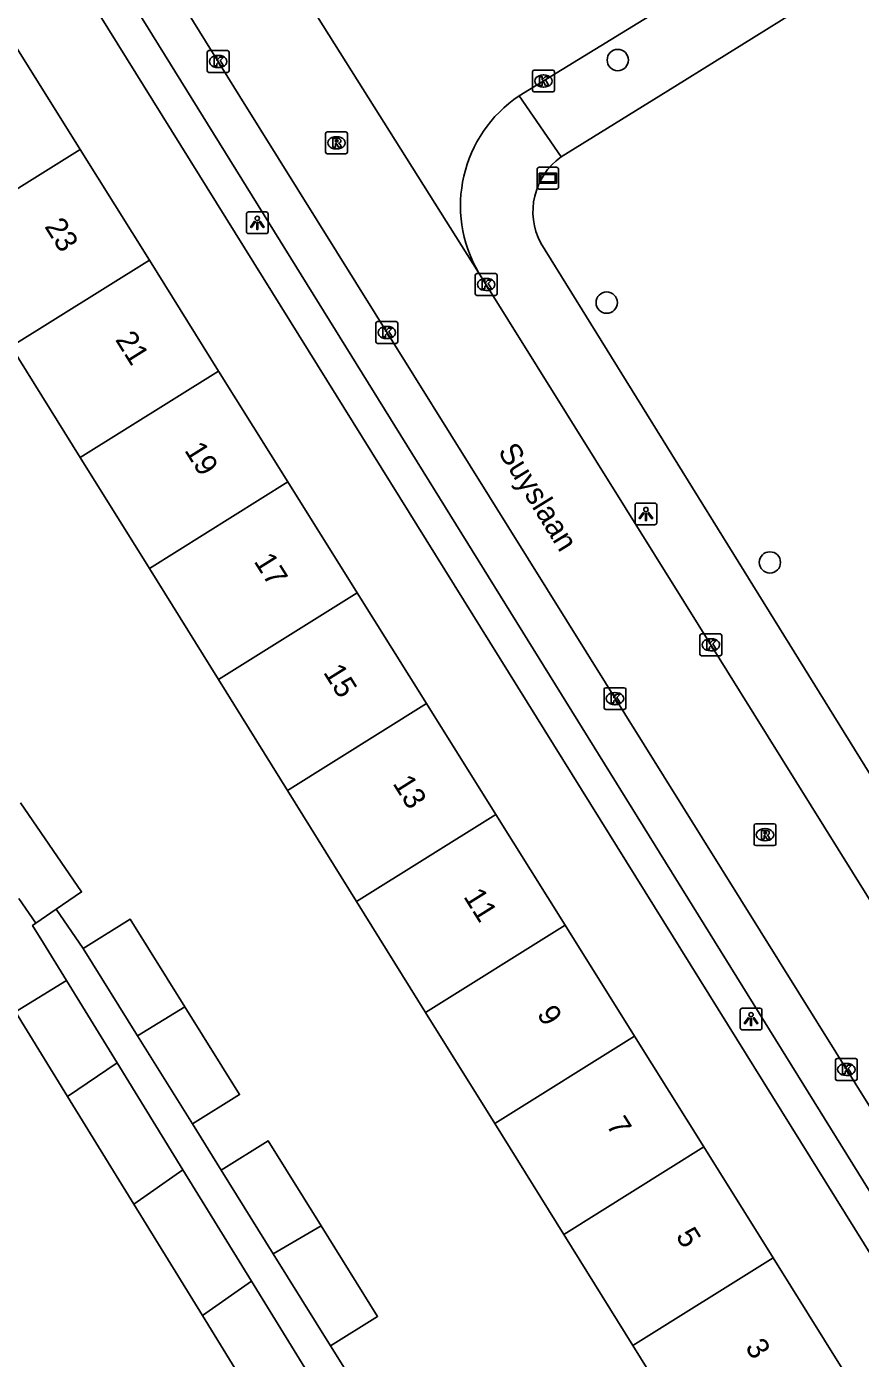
# Model space of a CAD drawing. Extents: x 160037 to 160839, y 385326 to 386441.
# Drawn here: x 160189.1 to 160227.4, y 386041.7 to 386102.8 of the extents above; entities that cross this region are included whole.
import ezdxf

# ---------------------------------------------------------------- set-up
doc = ezdxf.new("R2010")
doc.units = 0
for name, color, linetype in [('IMGEO_Boom', 7, 'Continuous'), ('IMGEO_Kolk', 7, 'Continuous'), ('IMGEO_Lichtpunt', 7, 'Continuous'), ('IMGEO_Openbare_ruimte_label', 7, 'Continuous'), ('IMGEO_Pand', 7, 'Continuous'), ('IMGEO_Pand_nummerreeks', 7, 'Continuous'), ('IMGEO_Rijbaan_lokaal_open', 7, 'Continuous'), ('IMGEO_Rioolput', 7, 'Continuous'), ('IMGEO_Straatnaambord', 7, 'Continuous'), ('IMGEO_Voetpad_open', 7, 'Continuous')]:
    doc.layers.add(name, color=color, linetype=linetype)

msp = doc.modelspace()

# ---------------------------------------------------------------- linework, layer by layer
at = {"layer": 'IMGEO_Boom'}
for centre in [(160216.279, 386101.253), (160215.77, 386090.121), (160223.261, 386078.194)]:
    msp.add_circle(centre, 0.489, dxfattribs=at)
at = {"layer": 'IMGEO_Kolk'}
for p, q in [((160197.508, 386101.686), (160198.36, 386101.686)), ((160197.433, 386100.76), (160197.433, 386101.612)), ((160197.921, 386101.466), (160197.946, 386101.466)), ((160198.434, 386101.612), (160198.434, 386100.76)), ((160198.36, 386100.686), (160197.508, 386100.686)), ((160197.944, 386100.906), (160197.919, 386100.906)), ((160212.367, 386099.863), (160212.367, 386100.715)), ((160212.442, 386100.789), (160213.294, 386100.789)), ((160212.855, 386100.569), (160212.88, 386100.569)), ((160213.368, 386100.715), (160213.368, 386099.863)), ((160213.294, 386099.789), (160212.442, 386099.789)), ((160212.878, 386100.009), (160212.853, 386100.009)), ((160209.735, 386090.527), (160209.735, 386091.379)), ((160209.81, 386091.453), (160210.662, 386091.453)), ((160210.223, 386091.233), (160210.248, 386091.233)), ((160210.736, 386091.379), (160210.736, 386090.527)), ((160210.246, 386090.673), (160210.221, 386090.673)), ((160210.662, 386090.453), (160209.81, 386090.453)), ((160205.176, 386088.321), (160205.176, 386089.173)), ((160205.251, 386089.247), (160206.103, 386089.247)), ((160205.664, 386089.027), (160205.689, 386089.027)), ((160206.177, 386089.173), (160206.177, 386088.321)), ((160206.103, 386088.247), (160205.251, 386088.247)), ((160205.687, 386088.467), (160205.662, 386088.467)), ((160220.051, 386073.989), (160220.051, 386074.841)), ((160220.126, 386074.915), (160220.978, 386074.915)), ((160221.052, 386074.841), (160221.052, 386073.989)), ((160220.562, 386074.135), (160220.537, 386074.135)), ((160220.539, 386074.695), (160220.564, 386074.695)), ((160220.978, 386073.915), (160220.126, 386073.915)), ((160215.647, 386071.521), (160215.647, 386072.373)), ((160215.722, 386072.447), (160216.574, 386072.447)), ((160216.648, 386072.373), (160216.648, 386071.521)), ((160216.158, 386071.667), (160216.133, 386071.667)), ((160216.135, 386072.227), (160216.16, 386072.227)), ((160216.574, 386071.447), (160215.722, 386071.447)), ((160226.27, 386054.5), (160226.27, 386055.352)), ((160226.345, 386055.426), (160227.197, 386055.426)), ((160226.758, 386055.206), (160226.783, 386055.206)), ((160227.271, 386055.352), (160227.271, 386054.5)), ((160226.781, 386054.646), (160226.756, 386054.646)), ((160227.197, 386054.426), (160226.345, 386054.426))]:
    msp.add_line(p, q, dxfattribs=at)
for points in [[(160197.508, 386101.686), (160198.36, 386101.686)], [(160197.433, 386100.76), (160197.433, 386101.612)], [(160197.754, 386101.386), (160197.877, 386101.386), (160197.877, 386101.235), (160198.007, 386101.386), (160198.171, 386101.386), (160198.025, 386101.235), (160198.178, 386100.986), (160198.026, 386100.986), (160197.941, 386101.15), (160197.877, 386101.083), (160197.877, 386100.986), (160197.754, 386100.986), (160197.754, 386101.386)], [(160198.434, 386101.612), (160198.434, 386100.76)], [(160198.36, 386100.686), (160197.508, 386100.686)], [(160212.367, 386099.863), (160212.367, 386100.715)], [(160212.442, 386100.789), (160213.294, 386100.789)], [(160212.688, 386100.489), (160212.811, 386100.489), (160212.811, 386100.338), (160212.941, 386100.489), (160213.105, 386100.489), (160212.959, 386100.338), (160213.112, 386100.089), (160212.96, 386100.089), (160212.875, 386100.253), (160212.811, 386100.186), (160212.811, 386100.089), (160212.688, 386100.089), (160212.688, 386100.489)], [(160213.368, 386100.715), (160213.368, 386099.863)], [(160213.294, 386099.789), (160212.442, 386099.789)], [(160209.735, 386090.527), (160209.735, 386091.379)], [(160209.81, 386091.453), (160210.662, 386091.453)], [(160210.736, 386091.379), (160210.736, 386090.527)], [(160210.056, 386091.153), (160210.179, 386091.153), (160210.179, 386091.002), (160210.309, 386091.153), (160210.473, 386091.153), (160210.327, 386091.002), (160210.48, 386090.753), (160210.328, 386090.753), (160210.243, 386090.917), (160210.179, 386090.85), (160210.179, 386090.753), (160210.056, 386090.753), (160210.056, 386091.153)], [(160210.662, 386090.453), (160209.81, 386090.453)], [(160205.176, 386088.321), (160205.176, 386089.173)], [(160205.251, 386089.247), (160206.103, 386089.247)], [(160205.497, 386088.947), (160205.62, 386088.947), (160205.62, 386088.796), (160205.75, 386088.947), (160205.914, 386088.947), (160205.768, 386088.796), (160205.921, 386088.547), (160205.769, 386088.547), (160205.684, 386088.711), (160205.62, 386088.644), (160205.62, 386088.547), (160205.497, 386088.547), (160205.497, 386088.947)], [(160206.177, 386089.173), (160206.177, 386088.321)], [(160206.103, 386088.247), (160205.251, 386088.247)], [(160220.051, 386073.989), (160220.051, 386074.841)], [(160220.126, 386074.915), (160220.978, 386074.915)], [(160221.052, 386074.841), (160221.052, 386073.989)], [(160220.372, 386074.615), (160220.495, 386074.615), (160220.495, 386074.464), (160220.625, 386074.615), (160220.789, 386074.615), (160220.643, 386074.464), (160220.796, 386074.215), (160220.644, 386074.215), (160220.559, 386074.379), (160220.495, 386074.312), (160220.495, 386074.215), (160220.372, 386074.215), (160220.372, 386074.615)], [(160220.978, 386073.915), (160220.126, 386073.915)], [(160215.647, 386071.521), (160215.647, 386072.373)], [(160215.722, 386072.447), (160216.574, 386072.447)], [(160216.648, 386072.373), (160216.648, 386071.521)], [(160215.968, 386072.147), (160216.091, 386072.147), (160216.091, 386071.996), (160216.221, 386072.147), (160216.385, 386072.147), (160216.239, 386071.996), (160216.392, 386071.747), (160216.24, 386071.747), (160216.155, 386071.911), (160216.091, 386071.844), (160216.091, 386071.747), (160215.968, 386071.747), (160215.968, 386072.147)], [(160216.574, 386071.447), (160215.722, 386071.447)], [(160226.27, 386054.5), (160226.27, 386055.352)], [(160226.345, 386055.426), (160227.197, 386055.426)], [(160227.271, 386055.352), (160227.271, 386054.5)], [(160226.591, 386055.126), (160226.714, 386055.126), (160226.714, 386054.975), (160226.844, 386055.126), (160227.008, 386055.126), (160226.862, 386054.975), (160227.015, 386054.726), (160226.863, 386054.726), (160226.778, 386054.89), (160226.714, 386054.823), (160226.714, 386054.726), (160226.591, 386054.726), (160226.591, 386055.126)], [(160227.197, 386054.426), (160226.345, 386054.426)]]:
    msp.add_lwpolyline(points, dxfattribs=at)
for centre, start, end in [((160197.51, 386101.61), 91.55205, 178.44795), ((160197.51, 386101.61), 91.55205, 178.44795), ((160198.358, 386101.61), 1.55205, 88.44795), ((160198.358, 386101.61), 1.55205, 88.44795), ((160197.51, 386100.762), 181.55205, 268.44795), ((160197.51, 386100.762), 181.55205, 268.44795), ((160198.358, 386100.762), 271.55205, 358.44795), ((160198.358, 386100.762), 271.55205, 358.44795), ((160212.444, 386100.713), 91.55205, 178.44795), ((160212.444, 386100.713), 91.55205, 178.44795), ((160213.292, 386100.713), 1.55205, 88.44795), ((160213.292, 386100.713), 1.55205, 88.44795), ((160212.444, 386099.865), 181.55205, 268.44795), ((160212.444, 386099.865), 181.55205, 268.44795), ((160213.292, 386099.865), 271.55205, 358.44795), ((160213.292, 386099.865), 271.55205, 358.44795), ((160209.812, 386091.377), 91.55205, 178.44795), ((160209.812, 386091.377), 91.55205, 178.44795), ((160210.66, 386091.377), 1.55205, 88.44795), ((160210.66, 386091.377), 1.55205, 88.44795), ((160209.812, 386090.529), 181.55205, 268.44795), ((160209.812, 386090.529), 181.55205, 268.44795), ((160210.66, 386090.529), 271.55205, 358.44795), ((160210.66, 386090.529), 271.55205, 358.44795), ((160205.253, 386089.171), 91.55205, 178.44795), ((160205.253, 386089.171), 91.55205, 178.44795), ((160206.101, 386089.171), 1.55205, 88.44795), ((160206.101, 386089.171), 1.55205, 88.44795), ((160205.253, 386088.323), 181.55205, 268.44795), ((160205.253, 386088.323), 181.55205, 268.44795), ((160206.101, 386088.323), 271.55205, 358.44795), ((160206.101, 386088.323), 271.55205, 358.44795), ((160220.128, 386074.839), 91.55205, 178.44795), ((160220.128, 386074.839), 91.55205, 178.44795), ((160220.976, 386074.839), 1.55205, 88.44795), ((160220.976, 386074.839), 1.55205, 88.44795), ((160220.128, 386073.991), 181.55205, 268.44795), ((160220.128, 386073.991), 181.55205, 268.44795), ((160220.976, 386073.991), 271.55205, 358.44795), ((160220.976, 386073.991), 271.55205, 358.44795), ((160215.724, 386072.371), 91.55205, 178.44795), ((160215.724, 386072.371), 91.55205, 178.44795), ((160216.572, 386072.371), 1.55205, 88.44795), ((160216.572, 386072.371), 1.55205, 88.44795), ((160215.724, 386071.523), 181.55205, 268.44795), ((160215.724, 386071.523), 181.55205, 268.44795), ((160216.572, 386071.523), 271.55205, 358.44795), ((160216.572, 386071.523), 271.55205, 358.44795), ((160226.347, 386055.35), 91.55205, 178.44795), ((160226.347, 386055.35), 91.55205, 178.44795), ((160227.195, 386055.35), 1.55205, 88.44795), ((160227.195, 386055.35), 1.55205, 88.44795), ((160226.347, 386054.502), 181.55205, 268.44795), ((160226.347, 386054.502), 181.55205, 268.44795), ((160227.195, 386054.502), 271.55205, 358.44795), ((160227.195, 386054.502), 271.55205, 358.44795)]:
    msp.add_arc(centre, 0.0765, start, end, dxfattribs=at)
for centre, major_axis, ratio, start_param, end_param in [((160197.92, 386101.186), (-0.387, 0.002), 0.722429, 4.712389, 7.853982), ((160197.945, 386101.186), (-0.39, 0.002), 0.717154, 1.570796, 4.712389), ((160212.854, 386100.289), (-0.387, 0.002), 0.722429, 4.712389, 7.853982), ((160212.879, 386100.289), (-0.39, 0.002), 0.717154, 1.570796, 4.712389), ((160210.222, 386090.953), (-0.387, 0.002), 0.722429, 4.712389, 7.853982), ((160210.247, 386090.953), (-0.39, 0.002), 0.717154, 1.570796, 4.712389), ((160205.663, 386088.747), (-0.387, 0.002), 0.722429, 4.712389, 7.853982), ((160205.688, 386088.747), (-0.39, 0.002), 0.717154, 1.570796, 4.712389), ((160220.538, 386074.415), (-0.387, 0.002), 0.722429, 4.712389, 7.853982), ((160220.563, 386074.415), (-0.39, 0.002), 0.717154, 1.570796, 4.712389), ((160216.134, 386071.947), (-0.387, 0.002), 0.722429, 4.712389, 7.853982), ((160216.159, 386071.947), (-0.39, 0.002), 0.717154, 1.570796, 4.712389), ((160226.757, 386054.926), (-0.387, 0.002), 0.722429, 4.712389, 7.853982), ((160226.782, 386054.926), (-0.39, 0.002), 0.717154, 1.570796, 4.712389)]:
    msp.add_ellipse(centre, major_axis=major_axis, ratio=ratio, start_param=start_param, end_param=end_param, dxfattribs=at)
at = {"layer": 'IMGEO_Lichtpunt'}
for p, q in [((160200.132, 386094.282), (160199.324, 386094.282)), ((160200.132, 386094.282), (160199.324, 386094.282)), ((160199.23, 386094.187), (160199.23, 386093.38)), ((160199.23, 386094.187), (160199.23, 386093.38)), ((160200.226, 386093.38), (160200.226, 386094.187)), ((160200.226, 386093.38), (160200.226, 386094.187)), ((160199.324, 386093.286), (160200.132, 386093.286)), ((160199.324, 386093.286), (160200.132, 386093.286)), ((160217.971, 386080.92), (160217.163, 386080.92)), ((160217.971, 386080.92), (160217.163, 386080.92)), ((160217.069, 386080.825), (160217.069, 386080.018)), ((160217.069, 386080.825), (160217.069, 386080.018)), ((160218.065, 386080.018), (160218.065, 386080.825)), ((160218.065, 386080.018), (160218.065, 386080.825)), ((160217.163, 386079.924), (160217.971, 386079.924)), ((160217.163, 386079.924), (160217.971, 386079.924)), ((160221.9, 386057.642), (160221.9, 386056.835)), ((160221.9, 386057.642), (160221.9, 386056.835)), ((160222.802, 386057.737), (160221.994, 386057.737)), ((160222.802, 386057.737), (160221.994, 386057.737)), ((160222.896, 386056.835), (160222.896, 386057.642)), ((160222.896, 386056.835), (160222.896, 386057.642)), ((160221.994, 386056.741), (160222.802, 386056.741)), ((160221.994, 386056.741), (160222.802, 386056.741))]:
    msp.add_line(p, q, dxfattribs=at)
for points in [[(160199.604, 386093.851), (160199.643, 386093.823), (160199.455, 386093.561), (160199.417, 386093.588), (160199.604, 386093.851)], [(160199.706, 386093.803), (160199.753, 386093.803), (160199.753, 386093.481), (160199.706, 386093.481), (160199.706, 386093.803)], [(160199.816, 386093.823), (160199.854, 386093.85), (160200.041, 386093.588), (160200.002, 386093.56), (160199.816, 386093.823)], [(160217.443, 386080.489), (160217.482, 386080.461), (160217.294, 386080.199), (160217.256, 386080.226), (160217.443, 386080.489)], [(160217.545, 386080.441), (160217.592, 386080.441), (160217.592, 386080.119), (160217.545, 386080.119), (160217.545, 386080.441)], [(160217.655, 386080.461), (160217.693, 386080.488), (160217.88, 386080.226), (160217.841, 386080.198), (160217.655, 386080.461)], [(160222.274, 386057.306), (160222.313, 386057.278), (160222.125, 386057.016), (160222.087, 386057.043), (160222.274, 386057.306)], [(160222.376, 386057.258), (160222.423, 386057.258), (160222.423, 386056.936), (160222.376, 386056.936), (160222.376, 386057.258)], [(160222.486, 386057.278), (160222.524, 386057.305), (160222.711, 386057.043), (160222.672, 386057.015), (160222.486, 386057.278)]]:
    msp.add_lwpolyline(points, dxfattribs=at)
for centre in [(160199.729, 386093.985), (160217.568, 386080.623), (160222.399, 386057.44)]:
    msp.add_circle(centre, 0.0994, dxfattribs=at)
for centre, start, end in [((160199.324, 386094.187), 90, 180), ((160199.324, 386094.187), 90, 180), ((160200.132, 386094.187), 0, 90), ((160200.132, 386094.187), 0, 90), ((160199.324, 386093.38), 180, 270), ((160199.324, 386093.38), 180, 270), ((160200.132, 386093.38), 270, 0), ((160200.132, 386093.38), 270, 360), ((160217.163, 386080.825), 90, 180), ((160217.163, 386080.825), 90, 180), ((160217.971, 386080.825), 0, 90), ((160217.971, 386080.825), 0, 90), ((160217.163, 386080.018), 180, 270), ((160217.163, 386080.018), 180, 270), ((160217.971, 386080.018), 270, 0), ((160217.971, 386080.018), 270, 360), ((160221.994, 386057.642), 90, 180), ((160221.994, 386057.642), 90, 180), ((160222.802, 386057.642), 0, 90), ((160222.802, 386057.642), 0, 90), ((160221.994, 386056.835), 180, 270), ((160221.994, 386056.835), 180, 270), ((160222.802, 386056.835), 270, 0), ((160222.802, 386056.835), 270, 360)]:
    msp.add_arc(centre, 0.0946, start, end, dxfattribs=at)
at = {"layer": 'IMGEO_Pand'}
for points in [[(160188.41, 386102.241), (160191.591, 386097.154)], [(160185.261, 386093.196), (160191.591, 386097.154)], [(160191.591, 386097.154), (160194.773, 386092.066)], [(160188.432, 386088.101), (160194.773, 386092.066)], [(160194.773, 386092.066), (160197.954, 386086.98)], [(160191.602, 386083.008), (160188.432, 386088.101)], [(160197.954, 386086.98), (160191.602, 386083.008)], [(160197.954, 386086.98), (160201.135, 386081.893)], [(160194.773, 386077.914), (160191.602, 386083.008)], [(160201.135, 386081.893), (160194.773, 386077.914)], [(160201.135, 386081.893), (160204.316, 386076.806)], [(160197.943, 386072.821), (160194.773, 386077.914)], [(160197.943, 386072.821), (160204.316, 386076.806)], [(160204.316, 386076.806), (160207.498, 386071.719)], [(160201.114, 386067.727), (160197.943, 386072.821)], [(160207.498, 386071.719), (160201.114, 386067.727)], [(160207.498, 386071.719), (160210.679, 386066.631)], [(160204.285, 386062.632), (160201.114, 386067.727)], [(160190.502, 386062.278), (160191.665, 386063.073), (160188.863, 386067.169)], [(160204.285, 386062.632), (160210.679, 386066.631)], [(160210.679, 386066.631), (160213.861, 386061.544)], [(160188.783, 386062.773), (160189.561, 386061.634)], [(160207.456, 386057.539), (160204.285, 386062.632)], [(160189.561, 386061.634), (160190.502, 386062.278)], [(160191.73, 386060.483), (160193.89, 386061.83), (160196.403, 386057.8)], [(160207.456, 386057.539), (160213.861, 386061.544)], [(160213.861, 386061.544), (160217.042, 386056.457)], [(160191.73, 386060.483), (160194.232, 386056.47)], [(160191.02, 386053.691), (160188.632, 386057.573), (160190.967, 386059.01)], [(160193.296, 386055.223), (160190.967, 386059.01)], [(160194.232, 386056.47), (160196.403, 386057.8)], [(160196.403, 386057.8), (160198.912, 386053.776), (160196.752, 386052.429)], [(160210.626, 386052.445), (160207.456, 386057.539)], [(160196.752, 386052.429), (160194.232, 386056.47)], [(160217.042, 386056.457), (160210.626, 386052.445)], [(160217.042, 386056.457), (160220.223, 386051.37)], [(160191.02, 386053.691), (160193.296, 386055.223)], [(160193.296, 386055.223), (160196.315, 386050.315)], [(160194.065, 386048.741), (160191.02, 386053.691)], [(160213.797, 386047.352), (160210.626, 386052.445)], [(160198.071, 386050.296), (160200.231, 386051.643), (160202.657, 386047.753)], [(160220.223, 386051.37), (160213.797, 386047.352)], [(160220.223, 386051.37), (160223.405, 386046.283)], [(160196.315, 386050.315), (160194.065, 386048.741)], [(160199.456, 386045.21), (160196.315, 386050.315)], [(160200.463, 386046.461), (160198.071, 386050.296)], [(160197.208, 386043.633), (160194.065, 386048.741)], [(160202.657, 386047.753), (160200.463, 386046.461)], [(160202.657, 386047.753), (160205.253, 386043.589), (160203.093, 386042.242)], [(160216.968, 386042.257), (160213.797, 386047.352)], [(160200.463, 386046.461), (160203.093, 386042.242)], [(160216.968, 386042.257), (160223.405, 386046.283)], [(160223.405, 386046.283), (160226.586, 386041.195)], [(160197.208, 386043.633), (160199.456, 386045.21)], [(160199.456, 386045.21), (160202.274, 386040.629)], [(160202.274, 386040.629), (160199.939, 386039.193), (160197.208, 386043.633)], [(160220.139, 386037.163), (160216.968, 386042.257)]]:
    msp.add_lwpolyline(points, dxfattribs=at)
at = {"layer": 'IMGEO_Rijbaan_lokaal_open'}
for points in [[(160191.24, 386111.976), (160198.933, 386099.578), (160234.281, 386042.907)], [(160228.648, 386109.969), (160211.756, 386099.608)], [(160200.958, 386105.712), (160201.013, 386105.608), (160209.89, 386091.505)], [(160209.89, 386091.505), (160219.316, 386076.396), (160240.647, 386042.176)]]:
    msp.add_lwpolyline(points, dxfattribs=at)
msp.add_arc((160215.112, 386094.569), 6.055, 123.66578, 210.39767, dxfattribs=at)
at = {"layer": 'IMGEO_Rioolput'}
for p, q in [((160202.938, 386097.954), (160203.79, 386097.954)), ((160202.863, 386097.028), (160202.863, 386097.88)), ((160203.351, 386097.734), (160203.376, 386097.734)), ((160203.864, 386097.88), (160203.864, 386097.028)), ((160203.79, 386096.954), (160202.938, 386096.954)), ((160203.374, 386097.174), (160203.349, 386097.174)), ((160222.611, 386066.198), (160223.463, 386066.198)), ((160222.536, 386065.272), (160222.536, 386066.124)), ((160223.024, 386065.978), (160223.049, 386065.978)), ((160223.537, 386066.124), (160223.537, 386065.272)), ((160223.463, 386065.198), (160222.611, 386065.198)), ((160223.047, 386065.418), (160223.022, 386065.418))]:
    msp.add_line(p, q, dxfattribs=at)
for points in [[(160202.938, 386097.954), (160203.79, 386097.954)], [(160202.863, 386097.028), (160202.863, 386097.88)], [(160203.452, 386097.652), (160203.2, 386097.654), (160203.2, 386097.254)], [(160203.2, 386097.254), (160203.324, 386097.254), (160203.324, 386097.416), (160203.335, 386097.416)], [(160203.378, 386097.573), (160203.324, 386097.573), (160203.324, 386097.492)], [(160203.324, 386097.492), (160203.376, 386097.492)], [(160203.382, 386097.387), (160203.453, 386097.254), (160203.593, 386097.254), (160203.528, 386097.38)], [(160203.864, 386097.88), (160203.864, 386097.028)], [(160203.79, 386096.954), (160202.938, 386096.954)], [(160222.611, 386066.198), (160223.463, 386066.198)], [(160222.536, 386065.272), (160222.536, 386066.124)], [(160223.125, 386065.896), (160222.873, 386065.898), (160222.873, 386065.498)], [(160222.873, 386065.498), (160222.997, 386065.498), (160222.997, 386065.66), (160223.008, 386065.66)], [(160223.051, 386065.817), (160222.997, 386065.817), (160222.997, 386065.736)], [(160222.997, 386065.736), (160223.049, 386065.736)], [(160223.055, 386065.631), (160223.126, 386065.498), (160223.266, 386065.498), (160223.201, 386065.624)], [(160223.537, 386066.124), (160223.537, 386065.272)], [(160223.463, 386065.198), (160222.611, 386065.198)]]:
    msp.add_lwpolyline(points, dxfattribs=at)
for centre, radius, start, end in [((160202.94, 386097.878), 0.0765, 91.55205, 178.44795), ((160202.94, 386097.878), 0.0765, 91.55205, 178.44795), ((160203.788, 386097.878), 0.0765, 1.55205, 88.44795), ((160203.788, 386097.878), 0.0765, 1.55205, 88.44795), ((160203.334, 386097.363), 0.0533, 26.02933, 88.69889), ((160203.36, 386097.681), 0.19, 274.7715, 282.96867), ((160203.384, 386097.477), 0.0964, 77.00612, 93.18647), ((160203.398, 386097.534), 0.0378, 276.66336, 79.67722), ((160203.451, 386097.542), 0.109, 350.36119, 89.41601), ((160203.449, 386097.542), 0.112, 277.58423, 350.98172), ((160203.433, 386097.327), 0.108, 29.51342, 73.79051), ((160202.94, 386097.03), 0.0765, 181.55205, 268.44795), ((160202.94, 386097.03), 0.0765, 181.55205, 268.44795), ((160203.788, 386097.03), 0.0765, 271.55205, 358.44795), ((160203.788, 386097.03), 0.0765, 271.55205, 358.44795), ((160222.613, 386066.122), 0.0765, 91.55205, 178.44795), ((160222.613, 386066.122), 0.0765, 91.55205, 178.44795), ((160223.461, 386066.122), 0.0765, 1.55205, 88.44795), ((160223.461, 386066.122), 0.0765, 1.55205, 88.44795), ((160223.007, 386065.607), 0.0533, 26.02933, 88.69889), ((160223.033, 386065.925), 0.19, 274.7715, 282.96867), ((160223.057, 386065.721), 0.0964, 77.00612, 93.18647), ((160223.071, 386065.778), 0.0378, 276.66336, 79.67722), ((160223.124, 386065.786), 0.109, 350.36119, 89.41601), ((160223.122, 386065.786), 0.112, 277.58423, 350.98172), ((160223.106, 386065.571), 0.108, 29.51342, 73.79051), ((160222.613, 386065.274), 0.0765, 181.55205, 268.44795), ((160222.613, 386065.274), 0.0765, 181.55205, 268.44795), ((160223.461, 386065.274), 0.0765, 271.55205, 358.44795), ((160223.461, 386065.274), 0.0765, 271.55205, 358.44795)]:
    msp.add_arc(centre, radius, start, end, dxfattribs=at)
for centre, major_axis, ratio, start_param, end_param in [((160203.35, 386097.454), (-0.387, 0.002), 0.722429, 4.712389, 7.853982), ((160203.375, 386097.454), (-0.39, 0.002), 0.717154, 1.570796, 4.712389), ((160223.023, 386065.698), (-0.387, 0.002), 0.722429, 4.712389, 7.853982), ((160223.048, 386065.698), (-0.39, 0.002), 0.717154, 1.570796, 4.712389)]:
    msp.add_ellipse(centre, major_axis=major_axis, ratio=ratio, start_param=start_param, end_param=end_param, dxfattribs=at)
at = {"layer": 'IMGEO_Straatnaambord'}
for p, q in [((160212.572, 386095.43), (160212.572, 386096.23)), ((160212.572, 386096.23), (160212.572, 386095.43)), ((160212.672, 386096.33), (160213.462, 386096.33)), ((160213.462, 386096.33), (160212.672, 386096.33)), ((160213.562, 386096.23), (160213.562, 386095.43)), ((160213.562, 386095.43), (160213.562, 386096.23)), ((160213.462, 386095.33), (160212.672, 386095.33)), ((160212.672, 386095.33), (160213.462, 386095.33))]:
    msp.add_line(p, q, dxfattribs=at)
for points in [[(160212.673, 386096.062), (160213.461, 386096.062), (160213.461, 386095.598), (160212.673, 386095.598), (160212.673, 386096.062)], [(160212.738, 386095.997), (160212.738, 386095.663), (160213.396, 386095.663), (160213.396, 386095.997), (160212.738, 386095.997)]]:
    msp.add_lwpolyline(points, dxfattribs=at)
for centre, start, end in [((160212.672, 386096.23), 90, 180), ((160212.672, 386096.23), 90, 180), ((160213.462, 386096.23), 0, 90), ((160213.462, 386096.23), 360, 90), ((160212.672, 386095.43), 180, 270), ((160212.672, 386095.43), 180, 270), ((160213.462, 386095.43), 270, 0), ((160213.462, 386095.43), 270, 0)]:
    msp.add_arc(centre, 0.1, start, end, dxfattribs=at)
at = {"layer": 'IMGEO_Voetpad_open'}
for points in [[(160186.576, 386112.811), (160233.001, 386038.217)], [(160230.344, 386045.305), (160191.916, 386107.243)], [(160213.673, 386096.809), (160218.901, 386100.039), (160229.816, 386106.842)], [(160213.673, 386096.809), (160211.756, 386099.608)], [(160243.449, 386043.345), (160212.738, 386092.855)], [(160190.502, 386062.278), (160191.73, 386060.483)], [(160190.967, 386059.01), (160189.915, 386060.72), (160189.415, 386061.534), (160189.561, 386061.634)], [(160196.752, 386052.429), (160198.071, 386050.296)], [(160203.093, 386042.242), (160204.413, 386040.108)]]:
    msp.add_lwpolyline(points, dxfattribs=at)
msp.add_arc((160215.474, 386094.295), 3.092, 125.62927, 207.76211, dxfattribs=at)

# ---------------------------------------------------------------- texts
at = {"layer": 'IMGEO_Openbare_ruimte_label'}
msp.add_text('Suyslaan', height=1, rotation=301.72006, dxfattribs=at).set_placement((160210.754, 386083.286))
at = {"layer": 'IMGEO_Pand_nummerreeks'}
for s, p in [('23', (160189.936, 386093.616)), ('21', (160193.183, 386088.423)), ('19', (160196.358, 386083.345)), ('17', (160199.546, 386078.248)), ('15', (160202.733, 386073.152)), ('13', (160205.92, 386068.055)), ('11', (160209.169, 386062.861)), ('9', (160212.539, 386057.472)), ('7', (160215.726, 386052.375)), ('5', (160218.914, 386047.278)), ('3', (160222.101, 386042.181))]:
    msp.add_text(s, height=1, rotation=302.02082, dxfattribs=at).set_placement(p)

doc.saveas('drawing.dxf')
